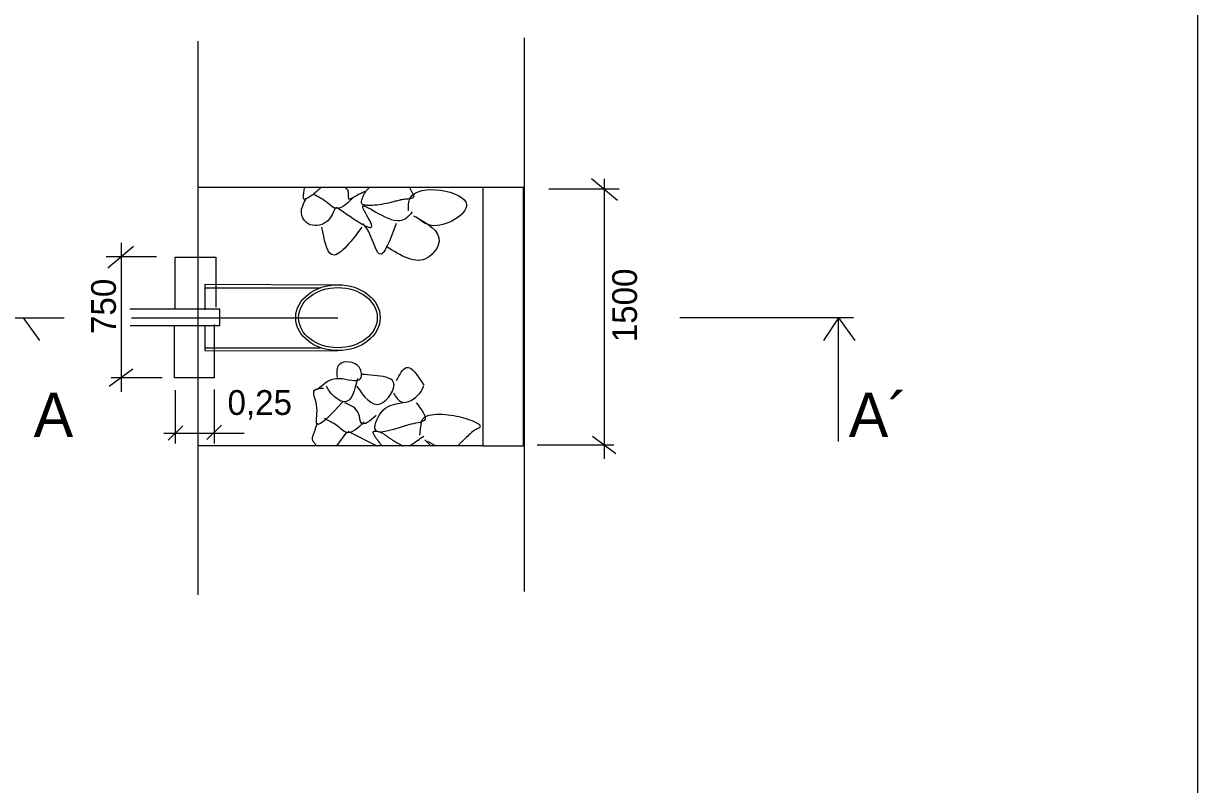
# Model space of a CAD drawing. Extents: x -463101.2 to -463058.2, y -1105044.4 to -1105011.4.
# Drawn here: x -463072.88 to -463058.66, y -1105032.87 to -1105023.66 of the extents above; entities that cross this region are included whole.
import ezdxf

# ---------------------------------------------------------------- set-up
doc = ezdxf.new("R2010")
doc.units = 0
doc.layers.add('Vrstva 14', color=7, linetype='Continuous')

msp = doc.modelspace()

# ---------------------------------------------------------------- linework, layer by layer
at = {"layer": 'Vrstva 14'}
for p, q in [((-463066.81653894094, -1105023.8280037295), (-463066.81653894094, -1105030.530418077)), ((-463070.767943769, -1105023.8700080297), (-463070.767943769, -1105030.5724223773)), ((-463065.9995876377, -1105025.5312775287), (-463065.6876479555, -1105025.7934618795)), ((-463065.8476655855, -1105025.5347331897), (-463065.8476655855, -1105028.924922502)), ((-463067.3181779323, -1105025.640027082), (-463070.76729409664, -1105025.640027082)), ((-463066.81899585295, -1105025.640027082), (-463067.3181779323, -1105025.640027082)), ((-463067.3181779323, -1105025.640027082), (-463067.3181779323, -1105028.7677961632)), ((-463066.8252356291, -1105028.7677961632), (-463066.8252356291, -1105025.6433654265)), ((-463066.5191157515, -1105025.6567217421), (-463065.66752041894, -1105025.6567217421)), ((-463071.5482691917, -1105026.3559565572), (-463071.8602088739, -1105026.618140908)), ((-463071.7001912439, -1105026.311280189), (-463071.7001912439, -1105028.1137976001)), ((-463071.2708198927, -1105026.4814007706), (-463071.8803364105, -1105026.4814007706)), ((-463070.6819263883, -1105027.121048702), (-463070.6819263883, -1105026.8113727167)), ((-463070.6819263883, -1105026.8113727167), (-463069.0859028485, -1105026.8173622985)), ((-463070.68181706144, -1105026.8542445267), (-463069.28329317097, -1105026.8542445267)), ((-463070.50305280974, -1105027.1127240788), (-463071.5921017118, -1105027.1127240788)), ((-463070.50305280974, -1105027.3108501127), (-463070.50305280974, -1105027.1127240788)), ((-463073.0745424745, -1105027.2180253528), (-463072.3904551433, -1105027.2178378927)), ((-463072.884326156, -1105027.219852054), (-463072.686938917, -1105027.4923547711)), ((-463071.5746303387, -1105027.217614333), (-463069.0725447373, -1105027.2169286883)), ((-463064.930306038, -1105027.215793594), (-463062.8268821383, -1105027.215217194)), ((-463063.01087736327, -1105027.219852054), (-463062.8134901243, -1105027.4923547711)), ((-463071.5890701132, -1105027.3108501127), (-463070.50305280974, -1105027.3108501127)), ((-463070.68442229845, -1105027.3104338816), (-463070.68442229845, -1105027.6159563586)), ((-463070.6848034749, -1105027.6121508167), (-463069.0753138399, -1105027.616520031)), ((-463070.68442229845, -1105027.580151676), (-463069.28642605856, -1105027.580151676)), ((-463071.5579987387, -1105027.8394733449), (-463071.84320073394, -1105028.0487452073)), ((-463071.20227326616, -1105027.9457070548), (-463071.8189882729, -1105027.9457070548)), ((-463071.0442134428, -1105028.0938394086), (-463071.0442134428, -1105028.7407540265)), ((-463070.57363015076, -1105028.0867051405), (-463070.57363015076, -1105028.738375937)), ((-463071.12913398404, -1105028.6998394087), (-463070.95313398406, -1105028.5258394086)), ((-463070.66055069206, -1105028.6927051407), (-463070.484550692, -1105028.5187051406)), ((-463071.1825495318, -1105028.6138394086), (-463070.20821344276, -1105028.6138394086)), ((-463068.96681185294, -1105028.5976509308), (-463069.0895970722, -1105028.7677961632)), ((-463068.95281185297, -1105028.5916509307), (-463068.6007251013, -1105028.7677961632)), ((-463068.02081185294, -1105028.6956509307), (-463067.94877049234, -1105028.7677961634)), ((-463065.9898580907, -1105028.6504018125), (-463065.7046560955, -1105028.8596736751)), ((-463067.3181779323, -1105028.7677961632), (-463070.76729409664, -1105028.7677961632)), ((-463067.88989417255, -1105028.7677961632), (-463067.98281185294, -1105028.7156509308)), ((-463067.3181779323, -1105028.7677961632), (-463066.8252356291, -1105028.7677961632)), ((-463066.6605284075, -1105028.7566355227), (-463065.7288685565, -1105028.7566355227))]:
    msp.add_line(p, q, dxfattribs=at)
msp.add_lwpolyline([(-463100.6606152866, -1105011.8801823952), (-463058.66061528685, -1105011.8801823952), (-463058.66061528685, -1105041.580182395), (-463100.6606152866, -1105041.580182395)], close=True, dxfattribs=at)
for points in [[(-463071.04638788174, -1105027.11890839), (-463071.04638788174, -1105026.4837396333), (-463070.5513656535, -1105026.4837396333), (-463070.5513656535, -1105027.089772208)], [(-463063.01087736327, -1105028.7141806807), (-463063.01087736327, -1105027.219852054), (-463063.1922151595, -1105027.4923547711)], [(-463070.5732345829, -1105027.3008608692), (-463070.5732345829, -1105027.9459002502), (-463071.05435102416, -1105027.9459002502), (-463071.05435102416, -1105027.3122774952)]]:
    msp.add_lwpolyline(points, dxfattribs=at)
for major_axis, ratio in [((0.5118952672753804, 0), 0.7792053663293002), ((0.47700487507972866, 0), 0.7630554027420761)]:
    msp.add_ellipse((-463069.0725447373, -1105027.2169286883), major_axis=major_axis, ratio=ratio, dxfattribs=at)
for points in [[(-463069.2778668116, -1105025.640027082), (-463069.3017140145, -1105025.6625953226), (-463069.32553427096, -1105025.6844926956), (-463069.37305636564, -1105025.7248573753), (-463069.42035793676, -1105025.7582861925), (-463069.443902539, -1105025.7715137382), (-463069.4556441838, -1105025.7771007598), (-463069.4615068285, -1105025.7796182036), (-463069.46443604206, -1105025.7808054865), (-463069.46590011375, -1105025.7813809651), (-463069.4666320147, -1105025.7816641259), (-463069.4673638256, -1105025.7819442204), (-463069.4709831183, -1105025.7831055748), (-463069.47426589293, -1105025.7837156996), (-463069.47986988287, -1105025.7833583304), (-463069.48756759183, -1105025.776865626), (-463069.4916096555, -1105025.7450284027), (-463069.48563339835, -1105025.6961698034), (-463069.4808082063, -1105025.6684003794), (-463069.4757822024, -1105025.6400270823)], [(-463068.74736382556, -1105025.6879442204), (-463068.83637421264, -1105025.7354741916), (-463068.8809168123, -1105025.7589626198), (-463068.9031579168, -1105025.7705318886), (-463068.9142659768, -1105025.776259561), (-463068.9253638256, -1105025.7819442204), (-463068.928545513, -1105025.7832982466), (-463068.93134039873, -1105025.783932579), (-463068.93586979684, -1105025.7831999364), (-463068.9413873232, -1105025.7748338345), (-463068.9438590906, -1105025.7393336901), (-463068.9455832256, -1105025.6956388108), (-463068.9501662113, -1105025.6770292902), (-463068.95936382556, -1105025.6639442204), (-463068.98984383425, -1105025.640027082)], [(-463068.2076965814, -1105025.640027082), (-463068.1573638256, -1105025.7359442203), (-463068.15528284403, -1105025.7406332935), (-463068.1541168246, -1105025.7449794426), (-463068.1543512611, -1105025.7527059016), (-463068.16383715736, -1105025.7647360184), (-463068.2088860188, -1105025.7786294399), (-463068.26967378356, -1105025.7856802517), (-463068.2988333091, -1105025.7891571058), (-463068.3118556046, -1105025.7913239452), (-463068.31782127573, -1105025.792569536), (-463068.32336382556, -1105025.7939442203), (-463068.350233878, -1105025.8011824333), (-463068.3775631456, -1105025.8083756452), (-463068.4332491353, -1105025.8222669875), (-463068.5462796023, -1105025.8455487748), (-463068.65685218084, -1105025.858028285), (-463068.7094658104, -1105025.8584167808), (-463068.7347980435, -1105025.8568331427), (-463068.7471822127, -1105025.8555574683), (-463068.7532990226, -1105025.8547937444), (-463068.75936382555, -1105025.8539442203), (-463068.7650533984, -1105025.8526644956), (-463068.7700202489, -1105025.8506431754), (-463068.77787318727, -1105025.8445328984), (-463068.78586784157, -1105025.8251418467), (-463068.77590688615, -1105025.7664781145), (-463068.74066867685, -1105025.6980681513), (-463068.7170667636, -1105025.6664943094), (-463068.7043819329, -1105025.6524652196), (-463068.69134093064, -1105025.640027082)], [(-463068.2173638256, -1105025.9239442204), (-463068.1973638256, -1105025.7679442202), (-463067.51536382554, -1105025.8459442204), (-463067.94336382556, -1105026.0999442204), (-463068.1193638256, -1105026.0019442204)], [(-463069.1033638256, -1105025.8839442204), (-463069.24336382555, -1105026.0779442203), (-463069.45536382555, -1105026.0659442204), (-463069.51536382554, -1105025.9479442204), (-463069.4573638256, -1105025.7779442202)], [(-463068.89336382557, -1105025.7659442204), (-463069.11336382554, -1105025.8899442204), (-463069.1953638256, -1105025.8299442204), (-463069.37336382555, -1105025.7239442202)], [(-463069.08936382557, -1105025.8779442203), (-463068.66536382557, -1105026.0899442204), (-463068.7713638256, -1105025.8779442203), (-463068.32336382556, -1105026.0419442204), (-463068.1693638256, -1105025.9359442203)], [(-463068.1573638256, -1105025.9819442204), (-463067.8473638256, -1105026.2959442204), (-463067.9833638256, -1105026.4899442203), (-463068.4893638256, -1105026.3539442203)], [(-463068.78136382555, -1105026.1199442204), (-463069.15136382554, -1105026.4519442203), (-463069.2673638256, -1105026.1199442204)], [(-463068.3693638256, -1105026.0779442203), (-463068.5713638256, -1105026.4459442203), (-463068.7233638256, -1105026.1379442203), (-463068.7713638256, -1105026.0779442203)], [(-463069.31881185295, -1105028.0816509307), (-463069.05881185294, -1105027.9516509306), (-463068.79881185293, -1105027.9516509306), (-463068.8108118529, -1105027.8216509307), (-463069.05881185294, -1105027.7856509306), (-463069.0828118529, -1105027.9396509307)], [(-463068.36281185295, -1105027.9756509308), (-463068.2448118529, -1105027.8216509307), (-463068.0328118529, -1105028.0336509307)], [(-463068.83481185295, -1105027.9516509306), (-463068.98881185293, -1105028.2356509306), (-463069.17681185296, -1105028.1056509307), (-463069.2128118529, -1105028.0456509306)], [(-463068.84681185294, -1105028.0456509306), (-463068.56281185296, -1105028.2596509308), (-463068.39881185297, -1105027.9996509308), (-463068.63481185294, -1105027.9156509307), (-463068.7888118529, -1105027.9036509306)], [(-463069.01281185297, -1105028.2356509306), (-463069.33081185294, -1105028.4956509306), (-463069.33081185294, -1105028.2716509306), (-463069.3548118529, -1105028.0936509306), (-463069.24881185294, -1105028.0696509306)], [(-463068.39881185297, -1105028.1296509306), (-463068.3048118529, -1105028.2356509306), (-463068.08081185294, -1105028.1296509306), (-463068.0328118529, -1105028.0456509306)], [(-463068.61081185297, -1105028.4016509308), (-463068.7888118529, -1105028.4956509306), (-463068.82281185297, -1105028.3776509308), (-463068.98881185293, -1105028.2476509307)], [(-463068.12681185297, -1105028.2476509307), (-463068.02081185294, -1105028.4496509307), (-463068.18681185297, -1105028.5076509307), (-463068.62281185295, -1105028.5676509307), (-463068.5168118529, -1105028.3296509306), (-463068.29281185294, -1105028.2476509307)], [(-463068.08081185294, -1105028.6376509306), (-463068.0761281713, -1105028.598585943), (-463068.07116933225, -1105028.5595375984), (-463068.0660317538, -1105028.52054592), (-463068.0608118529, -1105028.4816509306), (-463068.05879829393, -1105028.4713895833), (-463068.05563849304, -1105028.4617825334), (-463068.0460489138, -1105028.4444752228), (-463068.0149710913, -1105028.4170950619), (-463067.91467074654, -1105028.3881309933), (-463067.637090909, -1105028.4082551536), (-463067.40087154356, -1105028.4845772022), (-463067.3522717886, -1105028.5258604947), (-463067.3547993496, -1105028.5441411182), (-463067.36395123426, -1105028.5522984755), (-463067.37064685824, -1105028.5560823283), (-463067.37454304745, -1105028.5578944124), (-463067.3766305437, -1105028.558779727), (-463067.37881185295, -1105028.5596509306), (-463067.39391046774, -1105028.566366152), (-463067.4395339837, -1105028.5956176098), (-463067.5010479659, -1105028.6495341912), (-463067.56321333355, -1105028.7105454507), (-463067.59449639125, -1105028.740319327), (-463067.62588962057, -1105028.7677961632)], [(-463069.3301546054, -1105028.7677961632), (-463069.3418767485, -1105028.7551235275), (-463069.35288892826, -1105028.7422918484), (-463069.3709804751, -1105028.7161291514), (-463069.38082339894, -1105028.6892636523), (-463069.3815248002, -1105028.6755534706), (-463069.3806232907, -1105028.6686265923), (-463069.37881185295, -1105028.6616509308), (-463069.36458258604, -1105028.6191831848), (-463069.34990432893, -1105028.576727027), (-463069.33517983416, -1105028.5342328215), (-463069.32081185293, -1105028.4916509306)], [(-463068.7568118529, -1105028.4796509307), (-463068.97681185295, -1105028.6036509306), (-463069.05881185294, -1105028.5436509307), (-463069.23681185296, -1105028.4376509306)], [(-463068.5389295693, -1105028.7677961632), (-463068.57938853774, -1105028.7161609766), (-463068.5898979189, -1105028.702407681), (-463068.60018241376, -1105028.6884992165), (-463068.61034312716, -1105028.6744724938), (-463068.62048116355, -1105028.6603644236), (-463068.6276154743, -1105028.6494173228), (-463068.6338876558, -1105028.6379619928), (-463068.63952844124, -1105028.6261786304), (-463068.6447685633, -1105028.614247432), (-463068.6459071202, -1105028.6106162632), (-463068.64635421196, -1105028.6067682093), (-463068.6461065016, -1105028.6028839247), (-463068.6451606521, -1105028.5991440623), (-463068.6414651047, -1105028.5943380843), (-463068.63481185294, -1105028.5916509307), (-463068.6094860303, -1105028.5903716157), (-463068.58306967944, -1105028.5952324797), (-463068.56856236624, -1105028.6001795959), (-463068.5544898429, -1105028.6057345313), (-463068.5408384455, -1105028.6120876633), (-463068.52759451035, -1105028.6194293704), (-463068.49778964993, -1105028.6385279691), (-463068.4687649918, -1105028.6585002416), (-463068.43987599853, -1105028.6786062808), (-463068.41047813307, -1105028.6981061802), (-463068.3963422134, -1105028.707063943), (-463068.35412745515, -1105028.7329262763), (-463068.324869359, -1105028.7491927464), (-463068.2935286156, -1105028.7645553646), (-463068.28545971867, -1105028.7677961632)], [(-463068.21198124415, -1105028.7683936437), (-463068.20545195, -1105028.7659735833), (-463068.19924779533, -1105028.7630425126), (-463068.18681185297, -1105028.7556509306), (-463068.0328118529, -1105028.6496509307)]]:
    msp.add_spline(points, degree=3, dxfattribs=at)

# ---------------------------------------------------------------- texts
for s, p in [('1500', (-463065.45043481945, -1105027.514340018)), ('750', (-463071.7621403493, -1105027.414338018))]:
    msp.add_text(s, height=0.3, rotation=90, dxfattribs=at).set_placement(p)
for s, height, p in [('A', 0.536004, (-463072.7579395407, -1105028.6605798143)), ('0,25', 0.3, (-463070.4101170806, -1105028.3938394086)), ('A´', 0.536004, (-463062.884490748, -1105028.6605798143))]:
    msp.add_text(s, height=height, dxfattribs=at).set_placement(p)

doc.saveas('drawing.dxf')
